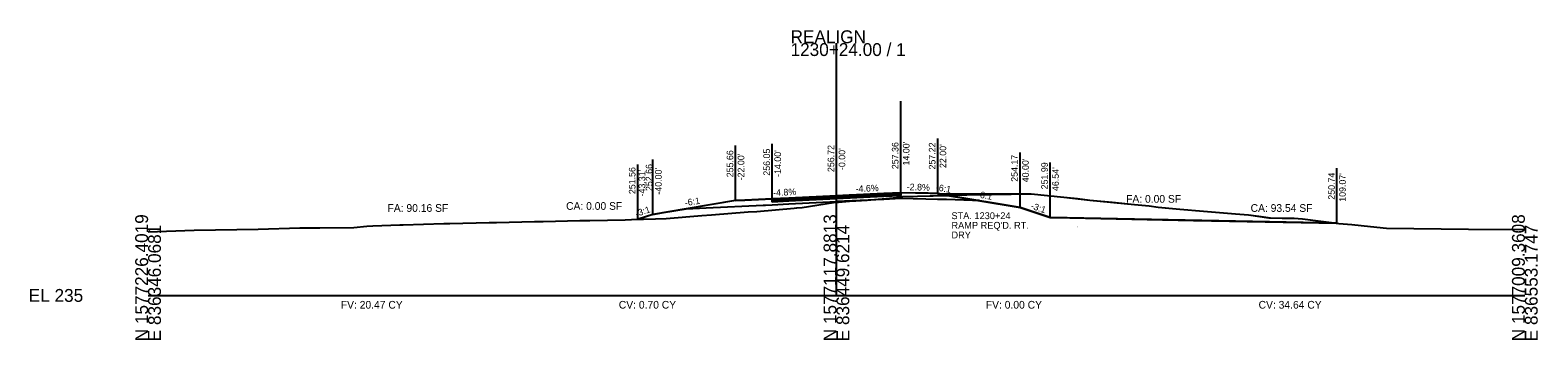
# Model space of a CAD drawing. Extents: x -26 to 6303, y -16 to 9563.
# Drawn here: x -25.7 to 302.8, y 8990.3 to 9057.8 of the extents above; entities that cross this region are included whole.
import ezdxf

# ---------------------------------------------------------------- set-up
doc = ezdxf.new("R2010")
doc.units = 0
for name, color, linetype in [('ASPHALT_19MM1', 7, 'Continuous'), ('ASPHALT_9_5MM1', 7, 'Continuous'), ('CONST_DCH', 7, 'Continuous'), ('CONST_LV3', 7, 'Continuous'), ('Draft_XS_Grid', 7, 'Continuous'), ('DTM_TEMP_DROP', 7, 'Continuous'), ('DTM_X_GROUND', 7, 'Continuous'), ('X_PROFILES_1', 7, 'Continuous'), ('X_TRANS_EOP', 7, 'Continuous'), ('XS_CELL', 7, 'Continuous'), ('XS_M_SHAPES_EARTHWORK', 7, 'Continuous'), ('XS_P_ASPHALT', 7, 'Continuous'), ('XS_P_DR_ASPHALT', 7, 'Continuous'), ('XS_P_DRIVEWAY', 7, 'Continuous'), ('XS_P_GROUND', 7, 'Continuous'), ('XS_P_SHOULDER', 7, 'Continuous'), ('XS_P_SUBGRADE_GRANULAR', 7, 'Continuous'), ('XS_P_TX_CLEARZONE', 7, 'Continuous'), ('XS_P_TX_FS_BS', 7, 'Continuous'), ('XS_PLAN_CLEAR_ZONE', 7, 'Continuous'), ('XS_SHEET_EW_TX_AREA', 7, 'Continuous'), ('XS_SHEET_EW_TX_VOLUME', 7, 'Continuous')]:
    doc.layers.add(name, color=color, linetype=linetype)

msp = doc.modelspace()

# ---------------------------------------------------------------- linework, layer by layer
at = {"layer": 'ASPHALT_19MM1'}
msp.add_lwpolyline([(136, 9020.51), (136, 9020.44), (139.62, 9020.62), (150, 9021.11), (160.36, 9021.61), (164.06, 9021.79), (164.06, 9021.86), (164.06, 9022.06), (160.36, 9021.88), (150, 9021.38), (139.62, 9020.89), (136, 9020.71), (136, 9020.51)], dxfattribs=at)
at = {"layer": 'ASPHALT_9_5MM1'}
msp.add_lwpolyline([(136, 9020.95), (136, 9020.92), (139.62, 9021.1), (150, 9021.59), (160.36, 9022.09), (164.06, 9022.27), (164.06, 9022.3), (164.06, 9022.39), (160.36, 9022.22), (150, 9021.72), (139.62, 9021.22), (136, 9021.05), (136, 9020.95)], dxfattribs=at)
at = {"layer": 'CONST_LV3'}
for points in [[(164, 9022.36), (152.79, 9021.85), (150, 9021.72)], [(172, 9022.17), (170.4, 9022.21), (164, 9022.36)], [(110, 9017.66), (111.89, 9017.98), (117.29, 9018.88)]]:
    msp.add_lwpolyline(points, dxfattribs=at)
at = {"layer": 'DTM_X_GROUND'}
msp.add_lwpolyline([(0, 9013.87), (10.03, 9014.23), (24.01, 9014.41), (33.09, 9014.77), (37.4, 9014.77), (44.84, 9014.79), (47.68, 9015.11), (49.01, 9015.14), (54.85, 9015.41), (55.57, 9015.41), (64.46, 9015.66), (65.77, 9015.66), (74.31, 9015.89), (75.94, 9015.89), (84.19, 9016.11), (86.09, 9016.11), (94.08, 9016.31), (96.23, 9016.31), (103.98, 9016.5), (105.33, 9016.56), (110.55, 9016.69), (112.93, 9016.79), (120.65, 9017.44), (122.79, 9017.54), (130.74, 9018.22), (132.67, 9018.31), (140.81, 9019.01), (141.4, 9019.1), (142.52, 9019.2), (143.9, 9019.41), (149.78, 9020.32), (150.48, 9020.35), (152.87, 9020.53), (154.25, 9020.62), (156.73, 9020.78), (162.38, 9021.28), (163.73, 9021.45), (164.47, 9021.55), (167.68, 9021.63), (178.44, 9021.9), (183.78, 9022), (192.41, 9022.15), (199.56, 9021.44), (202.56, 9021.11), (205.2, 9020.8), (214.95, 9019.83), (218.11, 9019.5), (220.08, 9019.22), (224.81, 9018.84), (229.95, 9018.35), (236.93, 9017.82), (239.8, 9017.55), (244.23, 9016.94), (244.58, 9016.91), (249.64, 9016.83), (249.77, 9016.82), (251.56, 9016.7), (259.48, 9015.69), (262.33, 9015.47), (266.39, 9015.01), (269.84, 9014.68), (287.74, 9014.46), (300, 9014.38)], dxfattribs=at)
at = {"layer": 'X_TRANS_EOP'}
msp.add_line((164, 9022.36), (164, 9042.36), dxfattribs=at)
at = {"layer": 'XS_CELL'}
for p, q in [((150, 9000), (150, 9055)), ((0, 9000), (150, 9000)), ((150, 9000), (300, 9000))]:
    msp.add_line(p, q, dxfattribs=at)
at = {"layer": 'XS_M_SHAPES_EARTHWORK'}
for points in [[(106.8, 9016.59), (110.55, 9016.69), (112.93, 9016.79), (120.65, 9017.44), (122.79, 9017.54), (130.74, 9018.22), (132.67, 9018.31), (140.81, 9019.01), (141.4, 9019.1), (142.52, 9019.2), (143.9, 9019.41), (149.78, 9020.32), (150.48, 9020.35), (152.87, 9020.53), (154.25, 9020.62), (156.73, 9020.78), (162.38, 9021.28), (163.73, 9021.45), (164.47, 9021.55), (167.68, 9021.63), (174.55, 9021.8), (173.91, 9021.91), (172.06, 9022.22), (169.98, 9022.26), (164.06, 9022.39), (164.06, 9022.3), (164.06, 9022.27), (164.06, 9022.11), (164.06, 9022.06), (164.06, 9021.86), (164.06, 9021.79), (160.36, 9021.61), (150, 9021.11), (139.62, 9020.62), (136, 9020.44), (136, 9020.51), (136, 9020.71), (136, 9020.77), (136, 9020.92), (136, 9020.95), (136, 9021.05), (130.07, 9020.76), (128, 9020.66), (117.29, 9018.88), (110, 9017.66)], [(106.69, 9016.56), (106.69, 9016.59), (106.8, 9016.59)]]:
    msp.add_lwpolyline(points, close=True, dxfattribs=at)
at = {"layer": 'XS_P_DRIVEWAY'}
msp.add_line((172, 9022.17), (192.35, 9022.15), dxfattribs=at)
at = {"layer": 'XS_P_GROUND'}
for points in [[(172, 9022.17), (190, 9019.17), (196.54, 9016.99)], [(174.55, 9021.8), (173.91, 9021.91), (172.06, 9022.22)], [(128, 9020.66), (110, 9017.66), (106.69, 9016.56)], [(196.54, 9016.99), (197.54, 9016.97)], [(197.54, 9016.97), (227.81, 9016.37), (259.07, 9015.74)]]:
    msp.add_lwpolyline(points, dxfattribs=at)
at = {"layer": 'XS_P_SHOULDER'}
for points in [[(172.06, 9022.22), (169.98, 9022.26), (164.06, 9022.39)], [(128, 9020.66), (130.07, 9020.76), (136, 9021.05)]]:
    msp.add_lwpolyline(points, dxfattribs=at)
at = {"layer": 'XS_P_SUBGRADE_GRANULAR'}
for points in [[(117.29, 9018.88), (121.62, 9019.08), (134, 9019.68), (134.52, 9019.7), (136, 9019.78)], [(136, 9019.78), (139.62, 9019.95), (150, 9020.45)], [(164.06, 9021.12), (160.36, 9020.94), (150, 9020.45)], [(172.2, 9020.9), (164.06, 9021.12)], [(181.08, 9020.66), (179.66, 9020.72), (174, 9020.94), (172.4, 9020.91), (172, 9020.9)]]:
    msp.add_lwpolyline(points, dxfattribs=at)
at = {"layer": 'XS_P_TX_CLEARZONE'}
for p, q in [((128, 9020.66), (128, 9032.66)), ((136, 9021.05), (136, 9033.05)), ((150, 9021.72), (150, 9033.72)), ((164, 9022.36), (164, 9034.36)), ((172.06, 9022.22), (172.06, 9034.22)), ((106.69, 9016.56), (106.69, 9028.56)), ((110, 9017.66), (110, 9029.66)), ((190, 9019.17), (190, 9031.17)), ((196.54, 9016.99), (196.54, 9028.99)), ((259.07, 9015.74), (259.07, 9027.74))]:
    msp.add_line(p, q, dxfattribs=at)
at = {"layer": 'XS_P_TX_FS_BS'}
msp.add_lwpolyline([(174.26, 9021.79), (178.44, 9021.9), (183.78, 9022), (188.1, 9022.07), (192.41, 9022.15), (199.56, 9021.44), (205.2, 9020.8), (210.08, 9020.31), (214.95, 9019.83), (218.11, 9019.5), (220.08, 9019.22), (222.44, 9019.03), (224.81, 9018.84), (229.95, 9018.35), (233.44, 9018.08), (236.93, 9017.82), (239.8, 9017.55), (242.02, 9017.25), (244.58, 9016.91), (247.11, 9016.87), (249.7, 9016.83), (251.56, 9016.7), (255.52, 9016.19), (259.07, 9015.74), (196.54, 9016.99), (190, 9019.17)], close=True, dxfattribs=at)
at = {"layer": 'XS_PLAN_CLEAR_ZONE'}
msp.add_lwpolyline([(136, 9020.77), (136, 9020.71), (139.62, 9020.89), (150, 9021.38), (160.36, 9021.88), (164.06, 9022.06), (164.06, 9022.11), (164.06, 9022.27), (160.36, 9022.09), (150, 9021.59), (139.62, 9021.1), (136, 9020.92), (136, 9020.77)], dxfattribs=at)

# ---------------------------------------------------------------- texts
at = {"layer": 'CONST_DCH'}
for p in [(149.92, 9021.6), (163.98, 9022.27), (135.92, 9020.93)]:
    msp.add_text('X', height=0.24, dxfattribs=at).set_placement(p)
at = {"layer": 'Draft_XS_Grid'}
msp.add_text('-', height=0.0001, dxfattribs=at).set_placement((0, 9000))
at = {"layer": 'DTM_TEMP_DROP'}
for p in [(171.92, 9022.05), (174.47, 9021.68), (106.61, 9016.44)]:
    msp.add_text('X', height=0.24, dxfattribs=at).set_placement(p)
at = {"layer": 'X_PROFILES_1'}
for p in [(171.92, 9022.05), (189.92, 9019.05)]:
    msp.add_text('X', height=0.24, dxfattribs=at).set_placement(p)
at = {"layer": 'XS_CELL'}
for s, p in [('REALIGN', (140, 9055)), ('1230+24.00 / 1', (140, 9052.2)), ('EL 235', (-26, 8998.6))]:
    msp.add_text(s, height=2.8, dxfattribs=at).set_placement(p)
for s, p in [('N 1577226.4019', (0, 8990)), ('E 836346.0681', (2.8, 8990)), ('N 1577117.8813', (150, 8990)), ('E 836449.6214', (152.8, 8990)), ('N 1577009.3608', (300, 8990)), ('E 836553.1747', (302.8, 8990))]:
    msp.add_text(s, height=2.8, rotation=90, dxfattribs=at).set_placement(p)
at = {"layer": 'XS_P_ASPHALT'}
msp.add_text('X', height=0.24, dxfattribs=at).set_placement((202.43, 9014.88))
at = {"layer": 'XS_P_DR_ASPHALT'}
msp.add_text('X', height=0.24, dxfattribs=at).set_placement((109.92, 9017.54))
at = {"layer": 'XS_P_DRIVEWAY'}
for s, p in [('STA. 1230+24', (175.06, 9016.63)), ("RAMP REQ'D. RT.", (175.06, 9014.53)), ('DRY', (175.06, 9012.43))]:
    msp.add_text(s, height=1.5, dxfattribs=at).set_placement(p)
at = {"layer": 'XS_P_SHOULDER'}
for p in [(171.98, 9022.1), (127.92, 9020.54)]:
    msp.add_text('X', height=0.24, dxfattribs=at).set_placement(p)
at = {"layer": 'XS_P_SUBGRADE_GRANULAR'}
for p in [(174.47, 9021.68), (106.61, 9016.44)]:
    msp.add_text('X', height=0.24, dxfattribs=at).set_placement(p)
at = {"layer": 'XS_P_TX_CLEARZONE'}
for s, p in [('255.66', (127.52, 9025.76)), ('256.05', (135.52, 9026.11)), ("-14.00'", (137.92, 9025.84)), ('256.72', (149.52, 9026.9)), ("-0.00'", (151.92, 9027.33)), ('257.36', (163.52, 9027.53)), ("14.00'", (165.92, 9028.33)), ('257.22', (171.58, 9027.46)), ("22.00'", (173.92, 9027.78)), ('252.66', (109.89, 9022.76)), ("-22.00'", (129.92, 9025.09)), ('254.17', (189.52, 9024.78)), ("40.00'", (191.92, 9024.67)), ('251.99', (196.06, 9023.13)), ('251.56', (106.21, 9022.09)), ("-43.31'", (108.34, 9021.58)), ("-40.00'", (111.92, 9021.98)), ("46.54'", (198.46, 9022.76)), ('250.74', (258.59, 9020.87)), ("109.07'", (260.99, 9020.42))]:
    msp.add_text(s, height=1.44, rotation=90, dxfattribs=at).set_placement(p)
at = {"layer": 'XS_P_TX_FS_BS'}
for s, rotation, p in [('-4.8%', 2.7481, (136.24, 9021.66)), ('-4.6%', 2.6318, (154.2, 9022.51)), ('-2.8%', 358.3999, (165.31, 9022.96)), ('-6:1', 350.5377, (171.58, 9022.9)), ('-6:1', 350.3359, (180.56, 9021.39)), ('-3:1', 18.4332, (106.43, 9017.11)), ('-6:1', 9.4642, (117.08, 9019.45)), ('-3:1', 341.565, (192.22, 9018.94))]:
    msp.add_text(s, height=1.44, rotation=rotation, dxfattribs=at).set_placement(p)
at = {"layer": 'XS_SHEET_EW_TX_AREA'}
for s, p in [('FA: 0.00 SF', (213.12, 9020.21)), ('FA: 90.16 SF', (52.18, 9018.22)), ('CA: 0.00 SF', (91.09, 9018.66)), ('CA: 93.54 SF', (240.25, 9018.22))]:
    msp.add_text(s, height=1.68, dxfattribs=at).set_placement(p)
at = {"layer": 'XS_SHEET_EW_TX_VOLUME'}
for s, p in [('FV: 20.47 CY', (42, 8997.12)), ('CV: 0.70 CY', (102.58, 8997.12)), ('FV: 0.00 CY', (182.55, 8997.12)), ('CV: 34.64 CY', (241.99, 8997.12))]:
    msp.add_text(s, height=1.68, dxfattribs=at).set_placement(p)

doc.saveas('drawing.dxf')
